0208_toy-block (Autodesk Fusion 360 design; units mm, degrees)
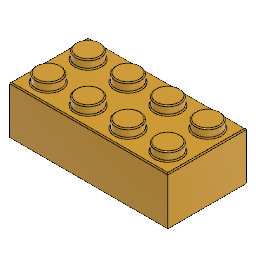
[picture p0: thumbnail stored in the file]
sketch "Sketch1" plane through (0, 0, 0) normal (0, 0, 1) x axis (1, 0, 0)
  line L1 (31.8, 0) -> (0, 0)
  line L2 (31.8, 15.8) -> (31.8, 0)
  line L3 (0, 15.8) -> (31.8, 15.8)
  line L4 (0, 0) -> (0, 15.8)
  point P1 (0, 0)
  point P2 (0, 0)
  point P3 (31.8, 0)
  point P5 (0, 15.8)
  horizontal L1
  vertical L2
  horizontal L3
  vertical L4
  coincident P1 P2
  dimension "d1" distance P2 P3 = 31.8
  dimension "d2" distance P2 P5 = 15.8
extrude "Extrude1" new body sketch "Sketch1" along normal blind 9.6
sketch "Sketch2" plane through (0, 0, 9.6) normal (0, 0, 1) x axis (-1, 0, 0)
  line L1 (0, 0) -> (0, -15.8)
  line L2 (-31.8, 0) -> (0, 0)
  line L3 (-31.8, -15.8) -> (-31.8, 0)
  line L4 (0, -15.8) -> (-31.8, -15.8)
  circle C1 centre (-3.9, -11.9) radius 2.5
  point P6 (-3.9, -11.9)
  dimension "d5" diameter C1 = 5
  dimension "d6" distance L4 P6 = 3.9
  dimension "d7" distance L1 P6 = 3.9
extrude "Extrude2" add sketch "Sketch2" profile of C1 along normal blind 1.7
rectangular_pattern "R-Pattern1" uSpaceDistance 24 vSpaceDistance -8
shell "Shell1" innerThickness 1.49
sketch "Sketch3" plane through (0, 0, 8.11) normal (0, 0, -1) x axis (1, 0, 0)
  line L1 (1.49, -14.31) -> (1.49, -1.49)
  line L2 (30.31, -14.31) -> (1.49, -14.31)
  line L3 (30.31, -1.49) -> (30.31, -14.31)
  line L4 (1.49, -1.49) -> (30.31, -1.49)
  line L5 (3.9, -11.9) -> (11.9, -3.9)
  circle C1 centre (27.9, -3.9) radius 1.01
  circle C2 centre (19.9, -3.9) radius 1.01
  circle C3 centre (11.9, -3.9) radius 1.01
  circle C4 centre (3.9, -3.9) radius 1.01
  circle C5 centre (27.9, -11.9) radius 1.01
  circle C6 centre (19.9, -11.9) radius 1.01
  circle C7 centre (11.9, -11.9) radius 1.01
  circle C8 centre (3.9, -11.9) radius 1.01
  circle C9 centre (7.9, -7.9) radius 3.15
  circle C10 centre (7.9, -7.9) radius 2.15
  point P4 (11.9, -3.9)
  point P14 (11.9, -3.9)
  point P9 (3.9, -11.9)
  point P15 (3.9, -11.9)
  point P16 (7.9, -7.9)
  coincident P4 P14
  coincident P9 P15
  midpoint L5 P16
  dimension "d15" diameter C9 = 6.3
  dimension "d16" = -1
extrude "Extrude3" add sketch "Sketch3" profile of C9 C10 along normal blind 8.1
rectangular_pattern "R-Pattern2" uSpaceDistance 16 vSpaceDistance 0
fillet "Fillet1" radius 0.2
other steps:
create_component "CreateComponent1"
